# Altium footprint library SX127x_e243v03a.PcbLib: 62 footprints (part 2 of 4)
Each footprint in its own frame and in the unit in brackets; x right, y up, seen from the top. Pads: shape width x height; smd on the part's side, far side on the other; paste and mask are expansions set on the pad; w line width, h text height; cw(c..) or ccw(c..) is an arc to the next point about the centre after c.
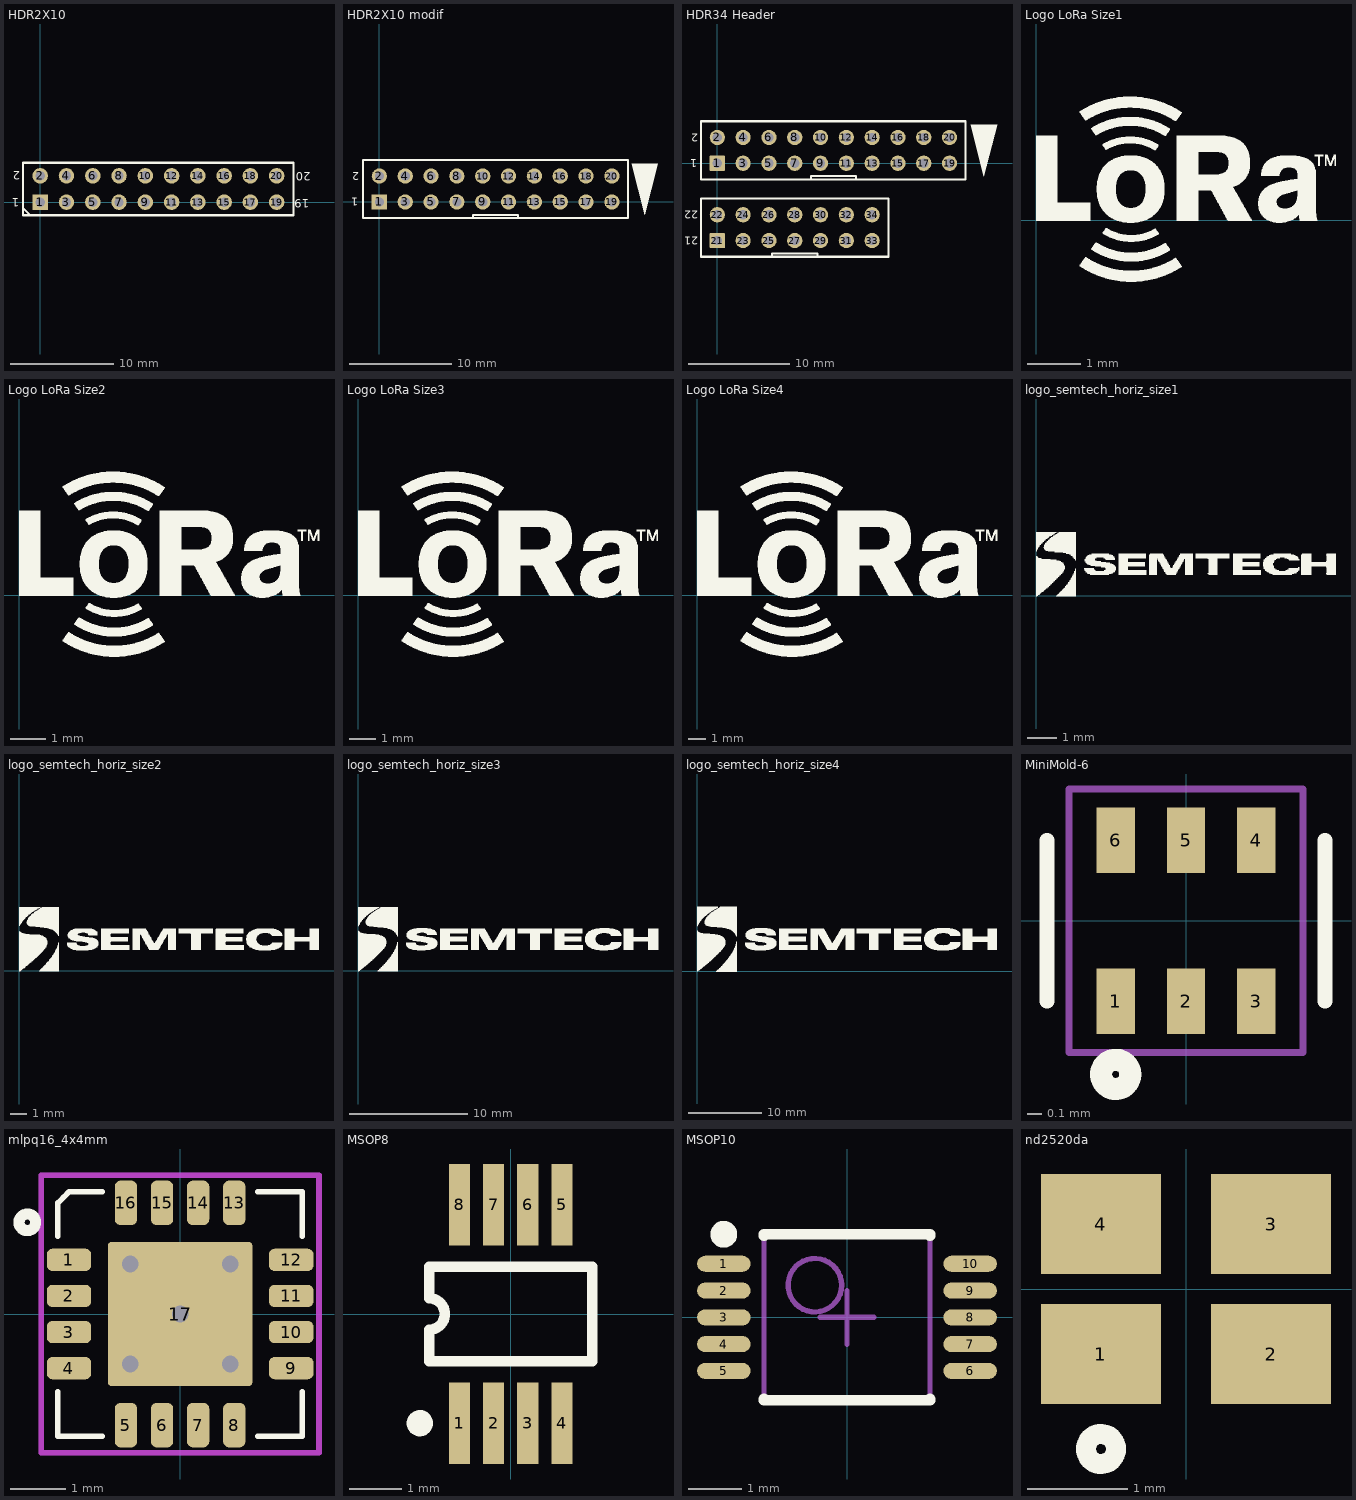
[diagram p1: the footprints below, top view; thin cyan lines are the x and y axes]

## HDR2X10 [mm] "Connector; Header; 10x2 Position"
pads (20):
  rect 1.5x1.5 hole 0.9 paste+0 mask+0.1: 1(0,0)
  round 1.5 hole 0.9 paste+0 mask+0.1: 2(0,2.54) 3(2.54,0) 4(2.54,2.54) 5(5.08,0) 6(5.08,2.54) 7(7.62,0) 8(7.62,2.54) 9(10.16,0) 10(10.16,2.54) 11(12.7,0) 12(12.7,2.54) 13(15.24,0) 14(15.24,2.54) 15(17.78,0) 16(17.78,2.54) 17(20.32,0) 18(20.32,2.54) 19(22.86,0) 20(22.86,2.54)
Top Overlay:
  lines w0.2: -1.65,-0.6 -1.015,-1.235 ; -1.65,-1.27 0.635,-1.27 24.5,-1.27 24.5,3.81 0.635,3.81 -1.65,3.81 -1.65,-1.27
  text "20" at 26.15,2.9 h0.8
  text "19" at 26,0.3 h0.8
  text "1" at -2.05,0.4 h0.8
  text "2" at -1.95,3 h0.8

## HDR2X10 modif [mm] "Connector; Header; 10x2 Position - modified"
pads (20):
  rect 1.5x1.5 hole 0.9: 1(0,0)
  round 1.5 hole 0.9: 2(0,2.54) 3(2.54,0) 4(2.54,2.54) 5(5.08,0) 6(5.08,2.54) 7(7.62,0) 8(7.62,2.54) 9(10.16,0) 10(10.16,2.54) 11(12.7,0) 12(12.7,2.54) 13(15.24,0) 14(15.24,2.54) 15(17.78,0) 16(17.78,2.54) 17(20.32,0) 18(20.32,2.54) 19(22.86,0) 20(22.86,2.54)
Top Overlay:
  region: 26.107,-1.275 27.394,3.775 24.82,3.775
  lines w0.2: 9.207,-1.587 9.207,-1.27 13.335,-1.27 13.652,-1.27 13.652,-1.587 ; -1.587,-1.587 24.447,-1.587 24.447,4.127 -1.587,4.127 -1.587,-1.587
  text "2" at -2,2.9 h0.8
  text "1" at -2.1,0.4 h0.8

## HDR34 Header [mm] "Connector; Header; 34 Position - SM12xx Header"
pads (34):
  rrect10% 1.5x1.5 hole 0.9 mask+0.05: 1(0,0) 21(0,-7.62)
  round 1.5 hole 0.9 mask+0.05: 2(0,2.54) 3(2.54,0) 4(2.54,2.54) 5(5.08,0) 6(5.08,2.54) 7(7.62,0) 8(7.62,2.54) 9(10.16,0) 10(10.16,2.54) 11(12.7,0) 12(12.7,2.54) 13(15.24,0) 14(15.24,2.54) 15(17.78,0) 16(17.78,2.54) 17(20.32,0) 18(20.32,2.54) 19(22.86,0) 20(22.86,2.54) 22(0,-5.08) 23(2.54,-7.62) 24(2.54,-5.08) 25(5.08,-7.62) 26(5.08,-5.08) 27(7.62,-7.62) 28(7.62,-5.08) 29(10.16,-7.62) 30(10.16,-5.08) 31(12.7,-7.62) 32(12.7,-5.08) 33(15.24,-7.62) 34(15.24,-5.08)
Top Overlay:
  region: 26.243,-1.275 27.53,3.775 24.956,3.775
  lines w0.2: 5.397,-9.207 5.397,-8.89 9.525,-8.89 9.842,-8.89 9.842,-9.207 ; 9.207,-1.587 9.207,-1.27 13.335,-1.27 13.652,-1.27 13.652,-1.587 ; -1.587,-9.207 -1.587,-3.492 16.828,-3.492 16.828,-9.207 -1.587,-9.207 ; -1.587,-1.587 24.447,-1.587 24.447,4.127 -1.587,4.127 -1.587,-1.587
  text "2" at -1.9,2.9 h0.8
  text "1" at -2,0.4 h0.8
  text "21" at -1.9,-7.25 h0.8
  text "22" at -1.9,-4.7 h0.8

## Logo LoRa Size1 [mm] "Logo LoRa Size1 - Top Overlay"
Top Overlay:
  drawing of 2375 lines, arcs and shapes, not listed

## Logo LoRa Size2 [mm] "Logo LoRa Size2 - Top Overlay"
Top Overlay:
  drawing of 2374 lines, arcs and shapes, not listed

## Logo LoRa Size3 [mm] "Logo LoRa Size3 - Top Overlay"
Top Overlay:
  drawing of 2375 lines, arcs and shapes, not listed

## Logo LoRa Size4 [mm] "Logo LoRa Size4 - Top Overlay"
Top Overlay:
  drawing of 2375 lines, arcs and shapes, not listed

## logo_semtech_horiz_size1 [mm] "Logo semtech horizontal - size1 - S"
Top Overlay:
  drawing of 453 lines, arcs and shapes, not listed

## logo_semtech_horiz_size2 [mm] "Logo semtech horizontal - size2 - M"
Top Overlay:
  drawing of 790 lines, arcs and shapes, not listed

## logo_semtech_horiz_size3 [mm] "Logo semtech horizontal - size3 - L"
Top Overlay:
  drawing of 1137 lines, arcs and shapes, not listed

## logo_semtech_horiz_size4 [mm] "Logo semtech horizontal - size4 - XL"
Top Overlay:
  drawing of 1852 lines, arcs and shapes, not listed

## MiniMold-6 [mm] "MiniMold-6 Package 1.5x1.1mm"
height 0.55
pads (6):
  rect 0.26x0.45 smd mask+0.05: 1(-0.48,-0.55) 2(0,-0.55) 3(0.48,-0.55) 4(0.48,0.55) 5(0,0.55) 6(-0.48,0.55)
Top Overlay:
  circle w0.15: c-0.48,-1.05 r0.1
  lines w0.1: -0.95,-0.55 -0.95,0.55 ; 0.95,-0.55 0.95,0.55
Mechanical 15:
  lines w0.05: -0.8,-0.9 -0.8,0.9 0.8,0.9 0.8,-0.9 -0.8,-0.9
3D body: height 1, standoff 0, extent -0.75,-0.55 0.75,0.55

## mlpq16_4x4mm [mm] "16 Leads, Body 4.0x4.0mm, Pitch 0.65mm, MLPQ16 - modifs pads size"
height 1
pads (17):
  rrect50% 0.8x0.4 smd mask+0.05: 1(-2,0.975) 2(-2,0.325) 3(-2,-0.325) 4(-2,-0.975) 9(2,-0.975) 10(2,-0.325) 11(2,0.325)
  rrect50% 0.4x0.8 smd mask+0.05: 5(-0.975,-2) 6(-0.325,-2) 7(0.325,-2) 8(0.975,-2) 13(0.975,2) 14(0.325,2) 15(-0.325,2) 16(-0.975,2)
  rrect50% 0.8x0.4 smd paste+0 mask+0.05: 12(2,0.975)
  rrect5% 2.6x2.6 smd paste-2.3 mask+0.05: 17(0,0)
via 0.9,0.9 diameter 0.5 hole 0.3
via -0.9,0.9 diameter 0.5 hole 0.3
via -0.9,-0.9 diameter 0.5 hole 0.3
via 0.9,-0.9 diameter 0.5 hole 0.3
via 0,0 diameter 0.5 hole 0.3
Top Overlay:
  circle w0.2: c-2.75,1.65 r0.15
  lines w0.1: -2.2,-1.4 -2.2,-2.2 -1.4,-2.2 ; -2.2,1.4 -2.2,2 -2.1,2.1 -2,2.2 -1.4,2.2 ; 1.4,-2.2 2.2,-2.2 2.2,-1.4 ; 1.4,2.2 2.2,2.2 2.2,1.4
Top Paste:
  region: -1.2,0.35 -0.45,0.35 -0.45,-0.35 -1.2,-0.35
  region: 0.35,-1.2 0.35,-0.45 -0.35,-0.45 -0.35,-1.2
  region: 1.2,0.35 0.45,0.35 0.45,-0.35 1.2,-0.35
  region: 0.35,0.45 0.35,1.2 -0.35,1.2 -0.35,0.45
Mechanical 15 keep-out:
  lines w0.1: -2.5,-2.5 -2.5,2.5 2.5,2.5 2.5,-2.5 -2.5,-2.5
3D body: height 1, standoff 0.05, extent -2,-2 2,2

## MSOP8 [mm] "Shrink Small Outline; 8 Leads; Body Width 3 mm; Pitch 0.65 mm"
height 1.17
pads (8):
  rect 0.4x1.55 smd: 1(-0.975,-2.075) 2(-0.325,-2.075) 3(0.325,-2.075) 4(0.975,-2.075) 5(0.975,2.075) 6(0.325,2.075) 7(-0.325,2.075) 8(-0.975,2.075)
Top Overlay:
  circle w0.25: c-1.725,-2.075 r0.125
  lines w0.2: -1.55,-0.9 -1.55,-0.3 ccw(c-1.55,0) -1.55,0.3 -1.55,0.9 1.55,0.9 1.55,-0.9 -1.55,-0.9

## MSOP10 [mm] "MSPO, 10-Leads, Body 3x3 mm, Pitch 0.5mm, IPC Medium Density"
height 0.8
pads (10):
  oval 1x0.3 smd: 1(-2.3,1) 2(-2.3,0.5) 3(-2.3,0) 4(-2.3,-0.5) 5(-2.3,-1) 6(2.3,-1) 7(2.3,-0.5) 8(2.3,0) 9(2.3,0.5) 10(2.3,1)
Top Overlay:
  circle w0.25: c-2.3,1.55 r0.125
  lines w0.2: -1.55,-1.525 -1.55,-1.55 1.55,-1.55 1.55,-1.525 ; -1.55,1.525 -1.55,1.55 1.55,1.55 1.55,1.525
Mechanical 13:
  circle w0.1: c-0.6,0.6 r0.5
  lines w0.1: -1.55,-1.55 -1.55,1.55 1.55,1.55 1.55,-1.55 -1.55,-1.55
Mechanical 15:
  lines w0.1: -0.5,0 0.5,0 ; 0,-0.5 0,0.5
3D body: height 0.8, standoff 0, extent -1.55,-1.55 1.55,1.55

## nd2520da [mm] "Crystal SMD 2.5x2.0mm"
height 0.7
pads (4):
  rect 1.2x1 smd mask+0.05: 1(-0.85,-0.65) 2(0.85,-0.65) 3(0.85,0.65) 4(-0.85,0.65)
Top Overlay:
  circle w0.2: c-0.85,-1.6 r0.15
3D body: height 1, standoff 0, extent -1.25,-1 1.25,1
